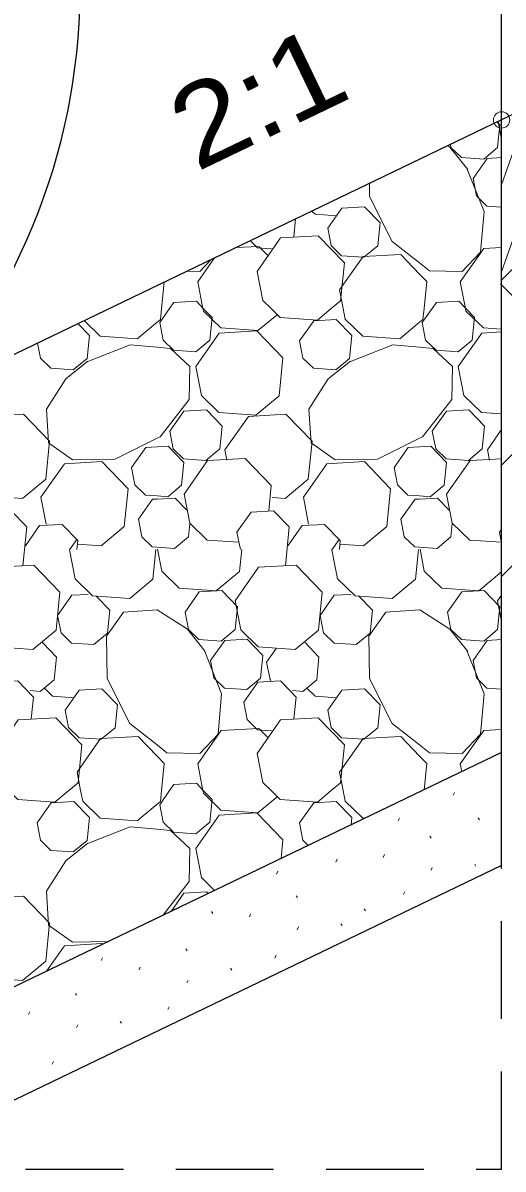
# Model space of a CAD drawing. Extents: x 685.4 to 719.4, y 1059.8 to 1105.8.
# Drawn here: x 696.79 to 697.704, y 1076.488 to 1078.67 of the extents above; entities that cross this region are included whole.
import ezdxf

# ---------------------------------------------------------------- set-up
doc = ezdxf.new("R2010")
doc.units = 0
doc.header["$LTSCALE"] = 0.062
doc.header["$PDMODE"] = 32
doc.header["$PDSIZE"] = 0.031
doc.linetypes.add('MEDIUM_DASHED', pattern=[4.5, 3, -1.5])
doc.layers.add('1', color=7, linetype='Continuous', lineweight=13)

msp = doc.modelspace()

# ---------------------------------------------------------------- linework, layer by layer
at = {"layer": '1', "lineweight": 25}
for p, q in [((698.87108, 1079.04808), (697.70108, 1078.48558)), ((697.70108, 1077.06575), (697.70108, 1078.741)), ((697.70108, 1078.4855), (696.15342, 1077.7415)), ((697.70108, 1077.28117), (696.49917, 1076.70333)), ((697.70108, 1077.06575), (696.49917, 1076.48792))]:
    msp.add_line(p, q, dxfattribs=at)
at = {"layer": '1'}
for p, q in [((697.70108, 1078.36217), (697.75317, 1078.51067)), ((697.70108, 1078.44875), (697.69458, 1078.48233)), ((697.70108, 1078.19642), (697.78592, 1078.43875)), ((697.84658, 1078.32667), (697.70075, 1078.18075)), ((697.30892, 1078.29708), (697.3055, 1078.26317)), ((697.1225, 1078.177), (697.15475, 1078.22292)), ((697.05883, 1078.17675), (697.05375, 1078.1265)), ((697.13242, 1078.1265), (697.12258, 1078.177)), ((697.3995, 1078.1265), (697.39267, 1078.16175)), ((697.63217, 1078.1265), (697.62233, 1078.177)), ((697.69917, 1078.17342), (697.7655, 1078.10717)), ((697.05017, 1078.09958), (697.069, 1078.1265)), ((697.54992, 1078.09958), (697.56883, 1078.1265)), ((697.84658, 1077.97375), (697.6995, 1077.82675)), ((697.674, 1077.8575), (697.70108, 1077.89592)), ((697.17825, 1077.83742), (697.17433, 1077.8575)), ((697.678, 1077.83742), (697.67408, 1077.8575)), ((696.83392, 1077.71608), (696.824, 1077.76717)), ((697.33367, 1077.71608), (697.32375, 1077.76717)), ((697.84658, 1077.76192), (697.70075, 1077.61608)), ((697.20367, 1077.66758), (697.19725, 1077.70075)), ((697.37808, 1077.66708), (697.39192, 1077.68667)), ((697.69342, 1077.57), (697.70108, 1077.58092)), ((697.70108, 1077.53092), (697.6935, 1077.57)), ((697.25367, 1077.45308), (697.272, 1077.47917)), ((696.89967, 1077.20867), (696.89283, 1077.24392)), ((697.13242, 1077.20867), (697.12258, 1077.25925)), ((697.3995, 1077.20867), (697.39267, 1077.24392)), ((697.62517, 1077.24467), (697.62233, 1077.25925)), ((697.05017, 1077.18175), (697.069, 1077.20867)), ((697.60875, 1077.19967), (697.61117, 1077.205)), ((697.50442, 1077.15083), (697.50683, 1077.15617)), ((697.65658, 1077.15667), (697.659, 1077.15308)), ((697.56475, 1077.12167), (697.56717, 1077.11808)), ((697.38542, 1077.07242), (697.38783, 1077.07775)), ((697.47567, 1077.08142), (697.478, 1077.08675)), ((697.64983, 1077.06842), (697.65225, 1077.06483)), ((697.27283, 1077.04958), (697.27525, 1077.05492)), ((697.56675, 1077.05683), (697.56917, 1077.06217)), ((697.31, 1077.00842), (697.31242, 1077.00483)), ((697.51425, 1077.0105), (697.51667, 1077.01575)), ((697.43958, 1076.9835), (697.442, 1076.97992)), ((697.14908, 1076.97808), (697.1515, 1076.9745)), ((697.221, 1076.96817), (697.22333, 1076.9735)), ((697.312, 1076.94358), (697.31442, 1076.94892)), ((697.39517, 1076.95517), (697.39758, 1076.95158)), ((697.09983, 1076.90725), (697.10225, 1076.90367)), ((697.26958, 1076.88967), (697.272, 1076.895)), ((696.93858, 1076.88475), (696.941, 1076.89008)), ((697.01083, 1076.86708), (697.01317, 1076.87233)), ((697.18492, 1076.87017), (697.18733, 1076.86667)), ((697.10183, 1076.8425), (697.10425, 1076.84783)), ((696.88958, 1076.82233), (696.892, 1076.81875)), ((696.80058, 1076.78208), (696.80292, 1076.78742)), ((697.06575, 1076.79175), (697.06817, 1076.79708)), ((696.89158, 1076.7575), (696.894, 1076.76283)), ((696.97475, 1076.76908), (696.97717, 1076.7655)), ((696.84567, 1076.68742), (696.84808, 1076.69275))]:
    msp.add_line(p, q, dxfattribs=at)
at = {"layer": '1', "linetype": 'MEDIUM_DASHED', "lineweight": 25}
for p, q in [((697.70108, 1076.48792), (697.70108, 1077.28117)), ((696.50892, 1076.48792), (697.70108, 1076.48792))]:
    msp.add_line(p, q, dxfattribs=at)
at = {"layer": '1'}
for points in [[(697.69267, 1078.48142), (697.69783, 1078.47608), (697.6935, 1078.43283), (697.667, 1078.41075), (697.62458, 1078.41383), (697.60467, 1078.43317), (697.60358, 1078.43875)], [(697.5985, 1078.43625), (697.60275, 1078.4335), (697.63658, 1078.39125)], [(697.64675, 1078.37417), (697.67367, 1078.41242), (697.70108, 1078.414)], [(697.63442, 1078.39467), (697.66767, 1078.31092), (697.661, 1078.23392), (697.62617, 1078.19725), (697.56375, 1078.19842), (697.54492, 1078.21317)], [(697.54492, 1078.21317), (697.49275, 1078.254), (697.44983, 1078.33975), (697.44942, 1078.36458)], [(697.70108, 1078.31967), (697.67317, 1078.32158), (697.65325, 1078.34092), (697.64675, 1078.37417)], [(697.38742, 1078.30317), (697.346, 1078.30617), (697.34, 1078.312)], [(697.26283, 1078.24033), (697.23642, 1078.24225), (697.22275, 1078.25558)], [(697.23558, 1078.19725), (697.28042, 1078.261), (697.352, 1078.26508), (697.40175, 1078.2135), (697.3945, 1078.14133), (697.37667, 1078.1265)], [(697.19517, 1078.24233), (697.23883, 1078.24483), (697.25517, 1078.22792)], [(697.39258, 1078.16175), (697.43733, 1078.22542), (697.50892, 1078.2295), (697.54492, 1078.19217)], [(697.62225, 1078.177), (697.66708, 1078.24075), (697.70108, 1078.24267)], [(697.14742, 1078.21933), (697.12642, 1078.19725), (697.10233, 1078.19767)], [(697.26233, 1078.1265), (697.24642, 1078.14192), (697.23567, 1078.19725)], [(697.54492, 1078.19217), (697.55867, 1078.17792), (697.5535, 1078.1265)], [(697.069, 1078.1265), (697.077, 1078.13783), (697.11992, 1078.14025), (697.13317, 1078.1265)], [(697.56883, 1078.1265), (697.57683, 1078.13783), (697.61967, 1078.14025), (697.63292, 1078.1265)], [(697.05375, 1078.1265), (697.05167, 1078.10575), (697.04517, 1078.10033)], [(697.13317, 1078.1265), (697.14975, 1078.10933), (697.14542, 1078.066), (697.11892, 1078.04392), (697.0765, 1078.047), (697.05667, 1078.06633), (697.05017, 1078.09958)], [(697.27292, 1078.11408), (697.23725, 1078.08433), (697.16658, 1078.08942), (697.13333, 1078.12167), (697.13242, 1078.1265)], [(697.37667, 1078.1265), (697.35033, 1078.10458), (697.27967, 1078.10967), (697.26233, 1078.1265)], [(697.54492, 1078.10033), (697.50725, 1078.069), (697.43658, 1078.07408), (697.40342, 1078.10633), (697.3995, 1078.1265)], [(697.5535, 1078.1265), (697.55142, 1078.10575), (697.54492, 1078.10033)], [(697.63292, 1078.1265), (697.6495, 1078.10933), (697.64517, 1078.066), (697.61867, 1078.04392), (697.57633, 1078.047), (697.55642, 1078.06633), (697.54992, 1078.09958)], [(697.70108, 1078.08692), (697.66633, 1078.08942), (697.63308, 1078.12167), (697.63217, 1078.1265)], [(696.89417, 1078.09767), (696.91625, 1078.07483), (696.91192, 1078.0315), (696.88542, 1078.0095), (696.84308, 1078.01258), (696.82317, 1078.03183), (696.8175, 1078.06075)], [(697.04517, 1078.10033), (697.0075, 1078.069), (696.93683, 1078.07408), (696.90642, 1078.10358)], [(697.11867, 1078.01617), (697.1635, 1078.07983), (697.23508, 1078.08392), (697.28475, 1078.03233), (697.2775, 1077.96017), (697.23333, 1077.92342), (697.16275, 1077.9285), (697.1295, 1077.96075), (697.11875, 1078.01617)], [(697.61842, 1078.01617), (697.66325, 1078.07983), (697.70108, 1078.082)], [(696.91017, 1078.02408), (696.994, 1078.05725), (697.04517, 1078.05283)], [(697.04517, 1078.05283), (697.07092, 1078.05058), (697.10758, 1078.01583), (697.10642, 1077.95333), (697.05092, 1077.88233), (697.04517, 1077.8795)], [(697.41, 1078.02408), (697.49375, 1078.05725), (697.54492, 1078.05283)], [(697.54492, 1078.05283), (697.57075, 1078.05058), (697.60733, 1078.01583), (697.60617, 1077.95333), (697.55067, 1077.88233), (697.54492, 1077.8795)], [(697.04517, 1077.8795), (696.96508, 1077.8395), (696.88417, 1077.83808), (696.83867, 1077.87042), (696.83433, 1077.93483), (696.87133, 1077.99242), (696.91358, 1078.02617)], [(697.54492, 1077.8795), (697.46483, 1077.8395), (697.384, 1077.83808), (697.33842, 1077.87042), (697.33408, 1077.93483), (697.37108, 1077.99242), (697.41342, 1078.02617)], [(697.70108, 1077.92575), (697.6625, 1077.9285), (697.62925, 1077.96075), (697.6185, 1078.01617)], [(696.6745, 1077.8575), (696.71925, 1077.92117), (696.79083, 1077.92525), (696.84058, 1077.87375), (696.83333, 1077.8015), (696.78917, 1077.76475), (696.76492, 1077.7665)], [(697.17425, 1077.8575), (697.21908, 1077.92117), (697.29058, 1077.92525), (697.34033, 1077.87375), (697.33308, 1077.8015), (697.28892, 1077.76475), (697.26467, 1077.7665)], [(696.99658, 1077.82383), (697.0235, 1077.86208), (697.04517, 1077.86333)], [(697.04517, 1077.86333), (697.06633, 1077.8645), (697.09617, 1077.83358), (697.09183, 1077.79025), (697.06533, 1077.76817), (697.04517, 1077.76967)], [(697.49633, 1077.82383), (697.52325, 1077.86208), (697.54492, 1077.86333)], [(697.54492, 1077.86333), (697.56617, 1077.8645), (697.59592, 1077.83358), (697.59158, 1077.79025), (697.56517, 1077.76817), (697.54492, 1077.76967)], [(696.82392, 1077.76717), (696.86875, 1077.83092), (696.94025, 1077.835), (696.99, 1077.78342), (696.98275, 1077.71125), (696.93858, 1077.6745), (696.89342, 1077.67775)], [(697.09658, 1077.77325), (697.14142, 1077.837), (697.213, 1077.84108), (697.26267, 1077.7895), (697.25783, 1077.74133)], [(697.32367, 1077.76717), (697.3685, 1077.83092), (697.44, 1077.835), (697.48975, 1077.78342), (697.4825, 1077.71125), (697.43833, 1077.6745), (697.39325, 1077.67775)], [(697.59633, 1077.77325), (697.64117, 1077.837), (697.70108, 1077.84042)], [(697.04517, 1077.76967), (697.023, 1077.77125), (697.00308, 1077.79058), (696.99658, 1077.82383)], [(697.54492, 1077.76967), (697.52275, 1077.77125), (697.50283, 1077.79058), (697.49633, 1077.82383)], [(697.04517, 1077.76375), (697.07933, 1077.76567), (697.1015, 1077.74267)], [(697.201, 1077.68133), (697.14067, 1077.68567), (697.10742, 1077.71792), (697.09667, 1077.77325)], [(697.54492, 1077.76375), (697.57917, 1077.76567), (697.60125, 1077.74267)], [(697.70075, 1077.68133), (697.64042, 1077.68567), (697.60717, 1077.71792), (697.59642, 1077.77325)], [(697.00958, 1077.72508), (697.0365, 1077.76325), (697.04517, 1077.76375)], [(697.50933, 1077.72508), (697.53625, 1077.76325), (697.54492, 1077.76375)], [(696.6975, 1077.70075), (696.72433, 1077.73892), (696.76725, 1077.74133), (696.79708, 1077.7105), (696.78975, 1077.63658)], [(697.04517, 1077.67183), (697.036, 1077.6725), (697.01608, 1077.69183), (697.00958, 1077.72508)], [(697.19725, 1077.70075), (697.22417, 1077.73892), (697.267, 1077.74133), (697.29683, 1077.7105), (697.2895, 1077.63658)], [(697.54492, 1077.67183), (697.53575, 1077.6725), (697.51583, 1077.69183), (697.50933, 1077.72508)], [(696.7945, 1077.67483), (696.82142, 1077.71308), (696.86433, 1077.7155), (696.89408, 1077.68458), (696.89233, 1077.66758)], [(697.10742, 1077.71733), (697.10483, 1077.6915), (697.07833, 1077.66942), (697.04517, 1077.67183)], [(697.29425, 1077.67483), (697.32117, 1077.71308), (697.36408, 1077.7155), (697.39392, 1077.68458), (697.39217, 1077.66758)], [(697.60717, 1077.71733), (697.60458, 1077.6915), (697.57817, 1077.66942), (697.54492, 1077.67183)], [(697.70108, 1077.67967), (697.697, 1077.70075), (697.70108, 1077.70658)], [(697.04283, 1077.66733), (697.03717, 1077.61108), (696.993, 1077.57442), (696.92233, 1077.5795), (696.88908, 1077.61167), (696.87833, 1077.66708), (696.89208, 1077.68667)], [(697.20633, 1077.66758), (697.20208, 1077.62567), (697.15792, 1077.589), (697.08725, 1077.59408), (697.05408, 1077.62625), (697.046, 1077.66808)], [(697.54258, 1077.66733), (697.53692, 1077.61108), (697.49275, 1077.57442), (697.42208, 1077.5795), (697.38892, 1077.61167), (697.37817, 1077.66708)], [(697.70108, 1077.62508), (697.65767, 1077.589), (697.58708, 1077.59408), (697.55383, 1077.62625), (697.54575, 1077.66808)], [(696.69392, 1077.57), (696.73867, 1077.63367), (696.81025, 1077.63775), (696.86, 1077.58625), (696.85275, 1077.514), (696.80858, 1077.47725), (696.73792, 1077.48233), (696.70467, 1077.51458), (696.694, 1077.57)], [(697.19367, 1077.57), (697.23842, 1077.63367), (697.31, 1077.63775), (697.35975, 1077.58625), (697.3525, 1077.514), (697.30833, 1077.47725), (697.23775, 1077.48233), (697.2045, 1077.51458), (697.19375, 1077.57)], [(696.85583, 1077.54217), (696.88275, 1077.58042), (696.91425, 1077.58217)], [(696.92933, 1077.579), (696.95542, 1077.55192), (696.95108, 1077.50858), (696.92458, 1077.4865), (696.88217, 1077.48958), (696.86233, 1077.50892), (696.85583, 1077.54217)], [(697.35558, 1077.54217), (697.3825, 1077.58042), (697.414, 1077.58217)], [(697.42908, 1077.579), (697.45517, 1077.55192), (697.45083, 1077.50858), (697.42433, 1077.4865), (697.382, 1077.48958), (697.36208, 1077.50892), (697.35558, 1077.54217)], [(697.04517, 1077.29542), (696.993, 1077.33617), (696.95008, 1077.422), (696.94867, 1077.50283), (696.98108, 1077.54842), (697.04517, 1077.55275)], [(697.04517, 1077.55275), (697.0455, 1077.55275), (697.103, 1077.51567), (697.13683, 1077.47342)], [(697.54492, 1077.29542), (697.49275, 1077.33617), (697.44983, 1077.422), (697.44842, 1077.50283), (697.48083, 1077.54842), (697.54492, 1077.55275)], [(697.54492, 1077.55275), (697.54525, 1077.55275), (697.60275, 1077.51567), (697.63658, 1077.47342)], [(696.82708, 1077.49033), (696.85358, 1077.46283), (696.84925, 1077.41958), (696.82275, 1077.3975), (696.8035, 1077.39892)], [(697.32683, 1077.49033), (697.35333, 1077.46283), (697.349, 1077.41958), (697.3225, 1077.3975), (697.30325, 1077.39892)], [(697.64675, 1077.45633), (697.67367, 1077.49458), (697.70108, 1077.49617)], [(697.13467, 1077.47683), (697.16792, 1077.39308), (697.16125, 1077.31608), (697.12642, 1077.2795), (697.06392, 1077.28067), (697.04517, 1077.29542)], [(697.63442, 1077.47683), (697.66767, 1077.39308), (697.661, 1077.31608), (697.62617, 1077.2795), (697.56375, 1077.28067), (697.54492, 1077.29542)], [(697.26158, 1077.4185), (697.26017, 1077.41992), (697.25367, 1077.45308)], [(697.70108, 1077.40183), (697.67317, 1077.40383), (697.65325, 1077.42317), (697.64675, 1077.45633)], [(696.71025, 1077.377), (696.73717, 1077.41525), (696.78008, 1077.41767), (696.80992, 1077.38675), (696.80575, 1077.34533)], [(697.21008, 1077.377), (697.23692, 1077.41525), (697.27983, 1077.41767), (697.30967, 1077.38675), (697.3055, 1077.34533)], [(696.88758, 1077.38533), (696.84625, 1077.38833), (696.83, 1077.40408)], [(697.38742, 1077.38533), (697.346, 1077.38833), (697.32975, 1077.40408)], [(697.26283, 1077.3225), (697.23642, 1077.32442), (697.21658, 1077.34375), (697.21008, 1077.377)], [(696.73583, 1077.2795), (696.78067, 1077.34317), (696.85225, 1077.34725), (696.90192, 1077.29575), (696.89467, 1077.2235), (696.87692, 1077.20867)], [(697.23558, 1077.2795), (697.28042, 1077.34317), (697.352, 1077.34725), (697.40175, 1077.29575), (697.3945, 1077.2235), (697.37667, 1077.20867)], [(696.89275, 1077.24392), (696.93758, 1077.30767), (697.00917, 1077.31167), (697.04517, 1077.27442)], [(697.1225, 1077.25925), (697.16733, 1077.32292), (697.23883, 1077.327), (697.25517, 1077.31008)], [(697.39258, 1077.24392), (697.43733, 1077.30767), (697.50892, 1077.31167), (697.54492, 1077.27442)], [(697.62225, 1077.25925), (697.66708, 1077.32292), (697.70108, 1077.32483)], [(697.04517, 1077.27442), (697.05892, 1077.26017), (697.05375, 1077.20867)], [(697.26233, 1077.20867), (697.24642, 1077.22408), (697.23567, 1077.2795)], [(697.54492, 1077.27442), (697.55867, 1077.26017), (697.55367, 1077.21025)], [(697.069, 1077.20867), (697.077, 1077.22), (697.11992, 1077.22242), (697.13317, 1077.20867)], [(696.87692, 1077.20867), (696.85058, 1077.18675), (696.77992, 1077.19183), (696.76258, 1077.20867)], [(697.04517, 1077.1825), (697.0075, 1077.15125), (696.93683, 1077.15633), (696.90358, 1077.1885), (696.89967, 1077.20867)], [(697.05375, 1077.20867), (697.05167, 1077.18792), (697.04517, 1077.1825)], [(697.13317, 1077.20867), (697.14975, 1077.1915), (697.14542, 1077.14825), (697.11892, 1077.12617), (697.0765, 1077.12925), (697.05667, 1077.14858), (697.05017, 1077.18175)], [(697.27292, 1077.19625), (697.23725, 1077.1665), (697.16658, 1077.17158), (697.13333, 1077.20383), (697.13242, 1077.20867)], [(697.37667, 1077.20867), (697.35033, 1077.18675), (697.27967, 1077.19183), (697.26233, 1077.20867)], [(697.44075, 1077.15592), (697.43658, 1077.15633), (697.40342, 1077.1885), (697.3995, 1077.20867)], [(697.31642, 1077.14733), (697.34333, 1077.1855), (697.38625, 1077.18792), (697.416, 1077.15708), (697.41475, 1077.1435)], [(697.11867, 1077.09833), (697.1635, 1077.162), (697.23508, 1077.16608), (697.28475, 1077.11458), (697.28125, 1077.07933)], [(696.91017, 1077.10625), (696.994, 1077.1395), (697.04517, 1077.13508)], [(697.04517, 1077.13508), (697.07092, 1077.13283), (697.10758, 1077.098), (697.10642, 1077.0355), (697.05583, 1076.971)], [(697.33308, 1077.10425), (697.32292, 1077.11408), (697.31642, 1077.14733)], [(696.95292, 1076.92142), (696.88417, 1076.92025), (696.83867, 1076.95258), (696.83433, 1077.017), (696.87133, 1077.07458), (696.91358, 1077.10842)], [(697.15475, 1077.01842), (697.1295, 1077.04292), (697.11875, 1077.09833)], [(696.6745, 1076.93967), (696.71925, 1077.00342), (696.79083, 1077.0075), (696.84058, 1076.95592), (696.83333, 1076.88367), (696.78917, 1076.847), (696.76492, 1076.84875)], [(697.07183, 1076.97867), (697.09617, 1077.01317), (697.13908, 1077.01558), (697.14217, 1077.0125)], [(696.83458, 1076.86458), (696.86875, 1076.91308), (696.94025, 1076.91717), (696.94142, 1076.91592)]]:
    msp.add_lwpolyline(points, dxfattribs=at)
for points in [[(697.37, 1078.27967), (697.39692, 1078.31783), (697.43975, 1078.32025), (697.46958, 1078.28942), (697.46525, 1078.24608), (697.43875, 1078.224), (697.39642, 1078.22708), (697.3765, 1078.24642)], [(697.31642, 1078.06508), (697.34333, 1078.10333), (697.38625, 1078.10575), (697.416, 1078.07483), (697.41167, 1078.0315), (697.38525, 1078.0095), (697.34283, 1078.01258), (697.32292, 1078.03183)], [(697.06925, 1077.89275), (697.09617, 1077.931), (697.13908, 1077.93342), (697.16892, 1077.9025), (697.16458, 1077.85925), (697.13808, 1077.83717), (697.09567, 1077.84025), (697.07575, 1077.85958)], [(697.56908, 1077.89275), (697.59592, 1077.931), (697.63883, 1077.93342), (697.66867, 1077.9025), (697.66433, 1077.85925), (697.63783, 1077.83717), (697.59542, 1077.84025), (697.57558, 1077.85958)], [(697.09842, 1077.54858), (697.12533, 1077.58683), (697.16825, 1077.58925), (697.19808, 1077.55833), (697.19375, 1077.515), (697.16725, 1077.49292), (697.12483, 1077.496), (697.10492, 1077.51533)], [(697.59817, 1077.54858), (697.62508, 1077.58683), (697.668, 1077.58925), (697.69783, 1077.55833), (697.6935, 1077.515), (697.667, 1077.49292), (697.62458, 1077.496), (697.60467, 1077.51533)], [(697.147, 1077.45633), (697.17392, 1077.49458), (697.21683, 1077.497), (697.24658, 1077.46608), (697.24225, 1077.42283), (697.21583, 1077.40075), (697.17342, 1077.40383), (697.1535, 1077.42317)], [(696.87025, 1077.36183), (696.89708, 1077.40008), (696.94, 1077.4025), (696.96983, 1077.37158), (696.9655, 1077.32825), (696.939, 1077.30625), (696.89658, 1077.30925), (696.87675, 1077.32858)], [(697.37, 1077.36183), (697.39692, 1077.40008), (697.43975, 1077.4025), (697.46958, 1077.37158), (697.46525, 1077.32825), (697.43875, 1077.30625), (697.39642, 1077.30925), (697.3765, 1077.32858)], [(696.81667, 1077.14733), (696.84358, 1077.1855), (696.88642, 1077.18792), (696.91625, 1077.15708), (696.91192, 1077.11375), (696.88542, 1077.09167), (696.84308, 1077.09475), (696.82317, 1077.11408)]]:
    msp.add_lwpolyline(points, close=True, dxfattribs=at)
at = {"layer": '1', "lineweight": 25}
msp.add_ellipse((695.69951, 1078.74096), major_axis=(1.19944, 0), ratio=0.999895, start_param=5.5737299, end_param=10.1752, dxfattribs=at)
at = {"layer": '1'}
msp.add_point((697.70108, 1078.4855), dxfattribs=at)

# ---------------------------------------------------------------- texts
at = {"layer": '1', "width": 1.15}
msp.add_text('2:1', height=0.156, rotation=25.677, dxfattribs=at).set_placement((697.12, 1078.38583))

doc.saveas('drawing.dxf')
